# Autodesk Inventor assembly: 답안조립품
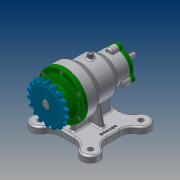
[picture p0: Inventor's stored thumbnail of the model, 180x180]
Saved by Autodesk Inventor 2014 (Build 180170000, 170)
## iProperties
Created: 2017-03
Part Number: 답안조립품
Document SubType Name: Assembly
Designer: Administrator
Author: Administrator
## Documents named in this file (14)
- C:\Users\Administrator\Desktop\470308V1011\답안조립품.iam
- C:\Users\Administrator\Desktop\470308V1011\본체.ipt
- C:\Users\Administrator\Desktop\470308V1011\뒤커버.ipt
- C:\Users\Administrator\Desktop\470308V1011\베어링-6200.ipt
- C:\Users\Administrator\Desktop\470308V1011\베어링-6203.ipt
- C:\Users\Administrator\Desktop\470308V1011\볼트 M4 x 12.ipt
- C:\Users\Administrator\Desktop\470308V1011\볼트 M5 x 10.ipt
- 볼트 M5 x 10.ipt
- C:\Users\Administrator\Desktop\470308V1011\스프로킷.ipt
- C:\Users\Administrator\Desktop\470308V1011\앞커버.ipt
- C:\Users\Administrator\Desktop\470308V1011\오일 실 10 20 7.ipt
- C:\Users\Administrator\Desktop\470308V1011\오일 실 17 30 8.ipt
- C:\Users\Administrator\Desktop\470308V1011\축.ipt
- C:\Users\Administrator\Desktop\470308V1011\키5x5.ipt
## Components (9 placed, 1 different names)
1. ISO 4762 M4 x 12:2 — 각도:3
2. ISO 4762 M4 x 12:3
3. ISO 4762 M4 x 12:4
4. ISO 4762 M4 x 12:5
5. ISO 4762 M4 x 12:6
6. ISO 4762 M4 x 12:7
7. ISO 4762 M4 x 12:1 — 각도:4
8. ISO 4762 M4 x 12:8
9. ISO 4762 M4 x 12:9
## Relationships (2: Angle 2)
- 각도:3 [Angle]: ISO 4762 M4 x 12:2
- 각도:4 [Angle]: ISO 4762 M4 x 12:1
